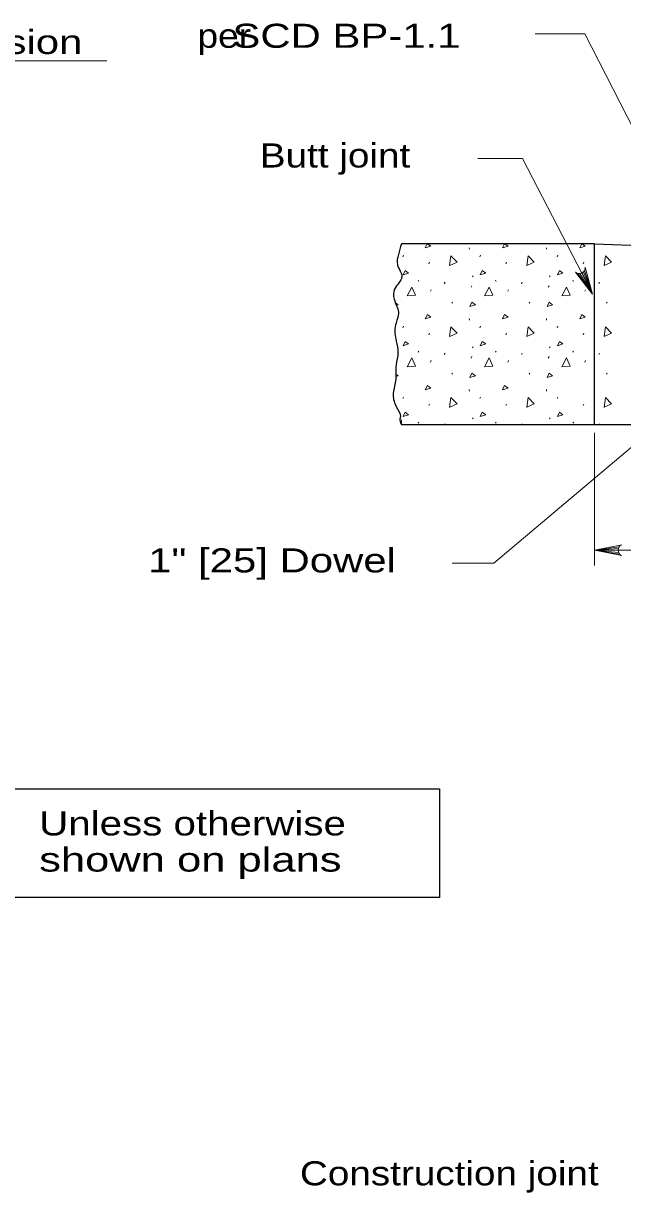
# Model space of a CAD drawing. Extents: x 1083.1 to 1117.1, y 719.4 to 763.4.
# Drawn here: x 1101.09 to 1104.96, y 728.72 to 736.3 of the extents above; entities that cross this region are included whole.
import ezdxf
from ezdxf.enums import TextEntityAlignment as Align

# ---------------------------------------------------------------- set-up
doc = ezdxf.new("R2010")
doc.units = 0
doc.header["$LTSCALE"] = 0.062
doc.layers.add('1', color=7, linetype='Continuous', lineweight=13)

msp = doc.modelspace()

# ---------------------------------------------------------------- linework, layer by layer
at = {"layer": '1'}
for p, q in [((1104.71917, 736.23), (1104.39942, 736.23)), ((1105.64367, 734.42225), (1104.71917, 736.23)), ((1098.96042, 736.05675), (1101.62633, 736.05675)), ((1104.31592, 735.42367), (1104.0265, 735.42367)), ((1104.73608, 734.61342), (1104.31592, 735.42367)), ((1103.68758, 734.84342), (1103.70033, 734.86992)), ((1104.18758, 734.84342), (1104.20033, 734.86992)), ((1104.68758, 734.84342), (1104.70033, 734.86992)), ((1103.54092, 734.78617), (1103.54533, 734.79617)), ((1103.97158, 734.84508), (1103.97275, 734.83508)), ((1104.04083, 734.78617), (1104.04525, 734.79617)), ((1104.47158, 734.84508), (1104.47275, 734.83508)), ((1104.54083, 734.78617), (1104.54525, 734.79617)), ((1103.7095, 734.74067), (1103.714, 734.75067)), ((1104.2095, 734.74067), (1104.214, 734.75067)), ((1104.7095, 734.74067), (1104.714, 734.75067)), ((1103.64167, 734.63367), (1103.64608, 734.627)), ((1103.99208, 734.66192), (1103.99658, 734.65525)), ((1104.14167, 734.63367), (1104.14608, 734.627)), ((1104.49208, 734.66192), (1104.49658, 734.65525)), ((1104.64167, 734.63367), (1104.64608, 734.627)), ((1104.67558, 734.67892), (1104.77033, 734.54492)), ((1104.68767, 734.67808), (1104.77033, 734.54492)), ((1104.70183, 734.682), (1104.77033, 734.54492)), ((1104.71117, 734.6885), (1104.77033, 734.54492)), ((1104.71867, 734.69833), (1104.77033, 734.54492)), ((1103.72067, 734.56325), (1103.72508, 734.57317)), ((1103.81058, 734.61192), (1103.815, 734.62192)), ((1103.98375, 734.58875), (1103.98817, 734.59875)), ((1104.22067, 734.56325), (1104.22508, 734.57317)), ((1104.31058, 734.61192), (1104.315, 734.62192)), ((1104.48375, 734.58875), (1104.48817, 734.59875)), ((1104.72067, 734.56325), (1104.72508, 734.57317)), ((1104.81058, 734.61192), (1104.815, 734.62192)), ((1103.85942, 734.49225), (1103.86383, 734.48558)), ((1104.35942, 734.49225), (1104.36383, 734.48558)), ((1104.85942, 734.49225), (1104.86383, 734.48558)), ((1103.54092, 734.32683), (1103.54533, 734.33683)), ((1103.97158, 734.38575), (1103.97275, 734.37575)), ((1104.04083, 734.32683), (1104.04525, 734.33683)), ((1104.47158, 734.38575), (1104.47275, 734.37575)), ((1104.54083, 734.32683), (1104.54525, 734.33683)), ((1103.7095, 734.28133), (1103.714, 734.29133)), ((1104.2095, 734.28133), (1104.214, 734.29133)), ((1104.7095, 734.28133), (1104.714, 734.29133)), ((1103.64167, 734.17433), (1103.64608, 734.16767)), ((1103.99208, 734.20258), (1103.99658, 734.19592)), ((1104.14167, 734.17433), (1104.14608, 734.16767)), ((1104.49208, 734.20258), (1104.49658, 734.19592)), ((1104.64167, 734.17433), (1104.64608, 734.16767)), ((1103.72067, 734.10392), (1103.72508, 734.11383)), ((1103.81058, 734.15258), (1103.815, 734.16258)), ((1103.98375, 734.12942), (1103.98817, 734.13942)), ((1104.22067, 734.10392), (1104.22508, 734.11383)), ((1104.31058, 734.15258), (1104.315, 734.16258)), ((1104.48375, 734.12942), (1104.48817, 734.13942)), ((1104.72067, 734.10392), (1104.72508, 734.11383)), ((1104.81058, 734.15258), (1104.815, 734.16258)), ((1103.85942, 734.03283), (1103.86383, 734.02617)), ((1104.35942, 734.03283), (1104.36383, 734.02617)), ((1104.85942, 734.03283), (1104.86383, 734.02617)), ((1103.54092, 733.8675), (1103.54533, 733.8775)), ((1103.97158, 733.92642), (1103.97275, 733.91642)), ((1104.04083, 733.8675), (1104.04525, 733.8775)), ((1104.47158, 733.92642), (1104.47275, 733.91642)), ((1104.54083, 733.8675), (1104.54525, 733.8775)), ((1103.7095, 733.822), (1103.714, 733.832)), ((1104.2095, 733.822), (1104.214, 733.832)), ((1104.7095, 733.822), (1104.714, 733.832)), ((1103.53283, 733.72892), (1103.53283, 733.69767)), ((1103.99208, 733.74325), (1103.99658, 733.73658)), ((1104.49208, 733.74325), (1104.49658, 733.73658)), ((1103.64167, 733.715), (1103.64608, 733.70833)), ((1103.8125, 733.69767), (1103.815, 733.70325)), ((1104.14167, 733.715), (1104.14608, 733.70833)), ((1104.3125, 733.69767), (1104.315, 733.70325)), ((1104.78267, 733.64558), (1104.78267, 732.78708)), ((1104.8125, 733.69767), (1104.815, 733.70325)), ((1104.943, 732.90775), (1104.78267, 732.88533)), ((1104.9375, 732.89667), (1104.78267, 732.88533)), ((1104.78267, 732.88533), (1105.99308, 732.88533)), ((1104.93592, 732.88533), (1104.78267, 732.88533)), ((1104.93875, 732.87092), (1104.78267, 732.88533)), ((1104.94483, 732.8605), (1104.78267, 732.88533))]:
    msp.add_line(p, q, dxfattribs=at)
at = {"layer": '1', "lineweight": 25}
for p, q in [((1104.78267, 734.86992), (1106.87633, 734.79125)), ((1104.64167, 733.715), (1104.64608, 733.70833))]:
    msp.add_line(p, q, dxfattribs=at)
for points in [[(1104.78267, 733.69767), (1104.78267, 734.86992), (1103.53283, 734.86992)], [(1106.03258, 733.69767), (1105.97908, 733.69767), (1104.78267, 733.69767), (1104.44383, 733.69767), (1103.53283, 733.69767)]]:
    msp.add_lwpolyline(points, dxfattribs=at)
at = {"layer": '1'}
for points in [[(1103.7025, 734.86992), (1103.72308, 734.8545), (1103.68758, 734.84342)], [(1104.2025, 734.86992), (1104.22308, 734.8545), (1104.18758, 734.84342)], [(1104.7025, 734.86992), (1104.72308, 734.8545), (1104.68758, 734.84342)], [(1103.84458, 734.72917), (1103.85342, 734.79267), (1103.89317, 734.75158), (1103.84558, 734.72958)], [(1104.34458, 734.72917), (1104.35342, 734.79267), (1104.39317, 734.75158), (1104.34558, 734.72958)], [(1104.84458, 734.72917), (1104.85342, 734.79267), (1104.89317, 734.75158), (1104.84558, 734.72958)], [(1104.6595, 734.6875), (1104.77033, 734.54492), (1104.72283, 734.71917)], [(1103.57083, 734.53325), (1103.60075, 734.58983), (1103.62417, 734.53775), (1103.572, 734.53325)], [(1104.07075, 734.53325), (1104.10075, 734.58983), (1104.12408, 734.53775), (1104.07192, 734.53325)], [(1104.57075, 734.53325), (1104.60075, 734.58983), (1104.62408, 734.53775), (1104.57192, 734.53325)], [(1103.49483, 734.48708), (1103.51158, 734.4745), (1103.50067, 734.47108)], [(1103.84458, 734.26983), (1103.85342, 734.33333), (1103.89317, 734.29225), (1103.84558, 734.27025)], [(1104.34458, 734.26983), (1104.35342, 734.33333), (1104.39317, 734.29225), (1104.34558, 734.27025)], [(1104.84458, 734.26983), (1104.85342, 734.33333), (1104.89317, 734.29225), (1104.84558, 734.27025)], [(1105.87192, 734.2705), (1104.13008, 732.8005), (1103.86075, 732.8005)], [(1103.57083, 734.07392), (1103.60075, 734.1305), (1103.62417, 734.07833), (1103.572, 734.07392)], [(1104.07075, 734.07392), (1104.10075, 734.1305), (1104.12408, 734.07833), (1104.07192, 734.07392)], [(1104.57075, 734.07392), (1104.60075, 734.1305), (1104.62408, 734.07833), (1104.57192, 734.07392)], [(1103.49633, 734.0265), (1103.51158, 734.01508), (1103.49592, 734.01017)], [(1103.84458, 733.81058), (1103.85342, 733.874), (1103.89317, 733.83292), (1103.84558, 733.81092)], [(1104.34458, 733.81058), (1104.35342, 733.874), (1104.39317, 733.83292), (1104.34558, 733.81092)], [(1104.84458, 733.81058), (1104.85342, 733.874), (1104.89317, 733.83292), (1104.84558, 733.81092)], [(1104.95975, 732.84992), (1104.78267, 732.88533), (1104.95975, 732.92067)]]:
    msp.add_lwpolyline(points, dxfattribs=at)
for points in [[(1103.54308, 734.66967), (1103.55642, 734.69742), (1103.57858, 734.68075)], [(1104.043, 734.66967), (1104.05633, 734.69742), (1104.07858, 734.68075)], [(1104.543, 734.66967), (1104.55633, 734.69742), (1104.57858, 734.68075)], [(1103.97592, 734.46342), (1103.98925, 734.49117), (1104.0115, 734.4745)], [(1104.47592, 734.46342), (1104.48925, 734.49117), (1104.5115, 734.4745)], [(1103.68758, 734.38408), (1103.70092, 734.41183), (1103.72308, 734.39517)], [(1104.18758, 734.38408), (1104.20092, 734.41183), (1104.22308, 734.39517)], [(1104.68758, 734.38408), (1104.70092, 734.41183), (1104.72308, 734.39517)], [(1103.54308, 734.21033), (1103.55642, 734.23808), (1103.57858, 734.22142)], [(1104.043, 734.21033), (1104.05633, 734.23808), (1104.07858, 734.22142)], [(1104.543, 734.21033), (1104.55633, 734.23808), (1104.57858, 734.22142)], [(1103.97592, 734.004), (1103.98925, 734.03175), (1104.0115, 734.01508)], [(1104.47592, 734.004), (1104.48925, 734.03175), (1104.5115, 734.01508)], [(1103.68758, 733.92475), (1103.70092, 733.9525), (1103.72308, 733.93583)], [(1104.18758, 733.92475), (1104.20092, 733.9525), (1104.22308, 733.93583)], [(1103.54308, 733.751), (1103.55642, 733.77875), (1103.57858, 733.76208)], [(1104.043, 733.751), (1104.05633, 733.77875), (1104.07858, 733.76208)], [(1104.543, 733.751), (1104.55633, 733.77875), (1104.57858, 733.76208)]]:
    msp.add_lwpolyline(points, close=True, dxfattribs=at)
at = {"layer": '1', "lineweight": 25}
msp.add_lwpolyline([(1100.40317, 731.34), (1103.7785, 731.34), (1103.7785, 730.63425), (1100.40317, 730.63425)], close=True, dxfattribs=at)
at = {"layer": '1'}
for centre, start, end in [((1104.68478, 734.71611), 228.63961, 4.46574), ((1104.97403, 732.88533), 112.08782, 247.91395)]:
    msp.add_arc(centre, 0.03822, start, end, dxfattribs=at)
at = {"layer": '1', "lineweight": 25}
msp.add_spline([(1103.53283, 734.86992), (1103.51358, 734.80167), (1103.50742, 734.73375), (1103.53517, 734.65658), (1103.48892, 734.57633), (1103.48583, 734.51158), (1103.51358, 734.42825), (1103.49508, 734.34492), (1103.49817, 734.24), (1103.5105, 734.16592), (1103.49817, 734.08567), (1103.49508, 733.98075), (1103.47967, 733.89125), (1103.50125, 733.811), (1103.52592, 733.75233), (1103.52283, 733.72767), (1103.53283, 733.69767)], degree=3, dxfattribs=at)

# ---------------------------------------------------------------- texts
at = {"layer": '1'}
for s, width, p in [('   SCD BP-1.1', 1.3, (1102.21258, 736.14)), ('per', 1.15, (1102.21258, 736.14)), ('Butt joint', 1.2, (1102.61608, 735.36458)), ('1" [25] Dowel', 1.3, (1101.89367, 732.74117)), ('Unless otherwise', 1.25, (1101.188, 731.03717)), ('shown on plans', 1.35, (1101.188, 730.80317)), ('Construction joint', 1.2, (1102.87575, 728.77033))]:
    msp.add_text(s, height=0.156, dxfattribs=dict(at, width=width)).set_placement(p)
at = {"layer": '1', "width": 1.3}
msp.add_text('1" [25] expansion', height=0.156, dxfattribs=at).set_placement((1100.42421, 736.09992), align=Align.CENTER)

doc.saveas('drawing.dxf')
